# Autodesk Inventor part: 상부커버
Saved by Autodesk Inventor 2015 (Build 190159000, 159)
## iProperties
Created: 2025-08
Part Number: 상부커버
Material: 일반
Document SubType Name: Modeling
Designer: user
Density: 1 g/cm^3
Appearance: 기본값
Author: jhkim
Creation Date: 2025-08-05
Sending System: Autodesk Inventor 2026
Preprocessor: ST-DEVELOPER v20.1
Author: user
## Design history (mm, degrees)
node "상부커버1"
node "솔리드1"
node "기준1"
